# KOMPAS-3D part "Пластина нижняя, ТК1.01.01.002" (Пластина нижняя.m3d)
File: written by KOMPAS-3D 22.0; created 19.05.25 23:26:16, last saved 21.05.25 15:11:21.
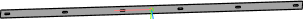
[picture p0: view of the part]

Document properties: Автор: user; Полное имя файла: КД\ТК1.01.01.002 - Пластина нижняя.cdw

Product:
- Part/product: Пластина нижняя  | designation ТК1.01.01.002
    Масса: 26.939167
    Форматы листов документа: A3

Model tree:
1. Эскиз:1
2. Элемент выдавливания:1
     Расстояние 1 = 5
3. Эскиз:2  (with: Элемент выдавливания:1)
4. Элемент выдавливания:2
     Расстояние 2 = 5
5. Массив по сетке:1  (with: Элемент выдавливания:2, Эскиз:2, Элемент выдавливания:1)  (6 pattern instances)
     Шаг 1 = 854; Угол раствора = 90
6. Эскиз:3  (with: Элемент выдавливания:1)
7. Элемент выдавливания:3
     Расстояние 2 = 5

Expressions: 4459+10; 59.5+5; H/2
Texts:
  ТК1.01.01.002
